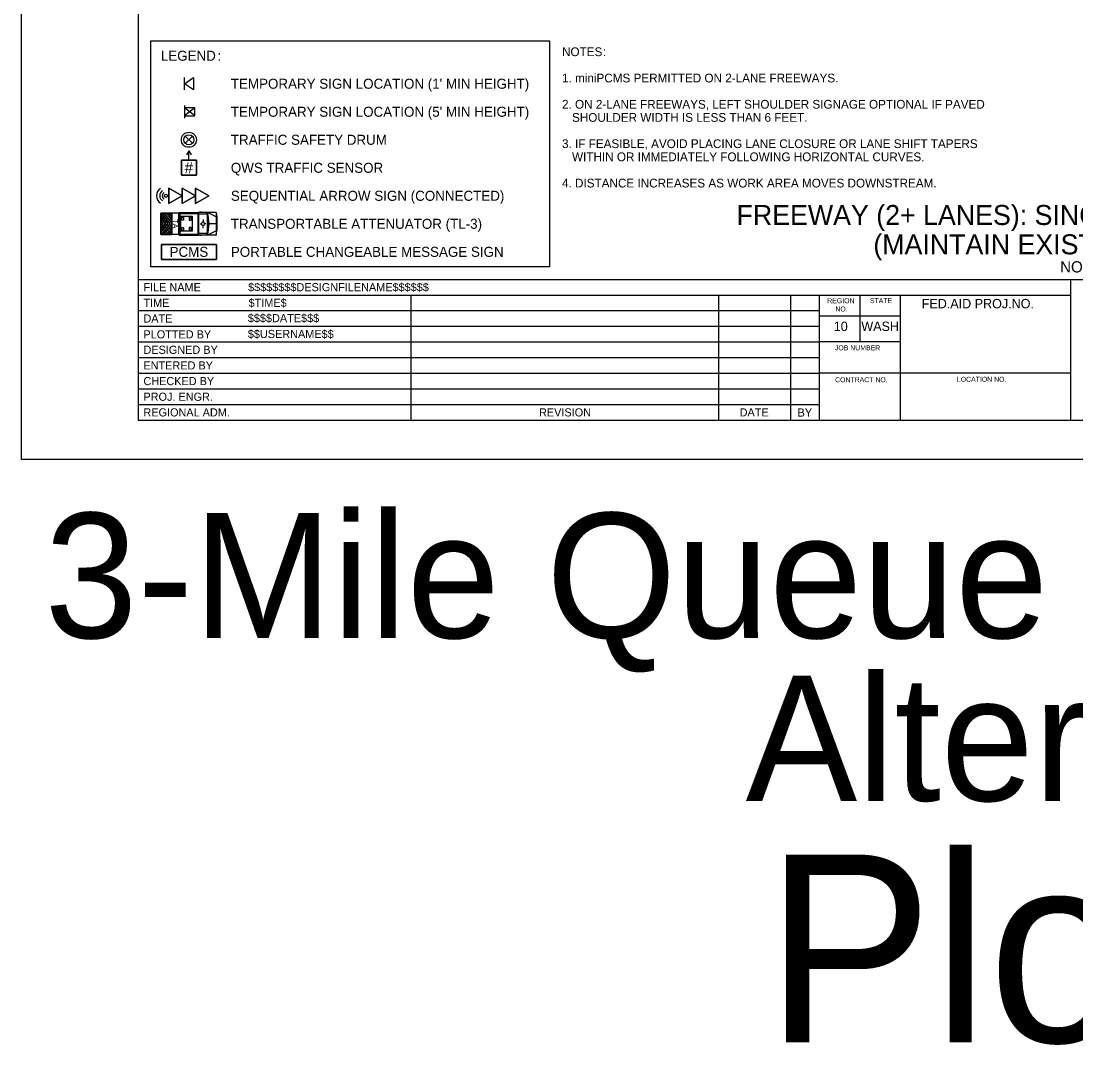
# Model space of a CAD drawing. Extents: x 99999 to 100116, y 99995 to 100013.
# Drawn here: x 100019.06 to 100027.5, y 99995.01 to 100003.19 of the extents above; entities that cross this region are included whole.
import ezdxf

# ---------------------------------------------------------------- set-up
doc = ezdxf.new("R2010")
doc.units = 0
for name, color, linetype in [('SH_DE_DetailHeading1Text', 7, 'Continuous'), ('SH_GI_GeneralNotesBodyText', 7, 'Continuous'), ('SH_GI_PlotLimits', 7, 'Continuous'), ('SH_GI_SheetBorder', 7, 'Continuous'), ('SH_GI_SheetLocationText', 7, 'Continuous'), ('SH_GI_SheetTextInCells', 7, 'Continuous'), ('SH_GI_TitleBlockText', 7, 'Continuous'), ('TR_WZ_PCMS', 7, 'Continuous'), ('TR_WZ_PortableSignMount5ftMinBlk-Wht', 7, 'Continuous'), ('TR_WZ_PortableSignMountBlk-Wht', 7, 'Continuous'), ('TR_WZ_SequentialArrowSign', 7, 'Continuous'), ('TR_WZ_TrafficSafetyDrum', 7, 'Continuous'), ('TR_WZ_TransportableAttenuator', 7, 'Continuous'), ('TR_WZ_WorkZoneDetails', 7, 'Continuous'), ('TR_WZ_WorkZoneTextCurrent', 7, 'Continuous')]:
    doc.layers.add(name, color=color, linetype=linetype)

msp = doc.modelspace()

# ---------------------------------------------------------------- linework, layer by layer
at = {"layer": 'SH_GI_PlotLimits'}
msp.add_lwpolyline([(100019.0625, 99999.6875), (100036.0625, 99999.6875), (100036.0625, 100010.6875), (100019.0625, 100010.6875)], close=True, dxfattribs=at)
at = {"layer": 'SH_GI_SheetBorder'}
for p, q in [((100020, 100010.375), (100020, 100000)), ((100020, 100001.1259), (100035.75, 100001.1259)), ((100027.4566, 100000), (100027.4566, 100001.1259)), ((100020, 100001.0008), (100027.4566, 100001.0008)), ((100022.179, 100001.0008), (100022.179, 100000)), ((100024.641, 100001.0008), (100024.641, 100000)), ((100025.2164, 100001.0008), (100025.2164, 100000)), ((100025.4451, 100001.0008), (100025.4451, 100000)), ((100025.7719, 100000.6255), (100025.7719, 100001.0008)), ((100026.0956, 100000), (100026.0956, 100001.0008)), ((100020, 100000.8757), (100022.1821, 100000.8757)), ((100022.1821, 100000.8757), (100025.4466, 100000.8757)), ((100026.0958, 100000.831), (100025.4466, 100000.831)), ((100020, 100000.7506), (100022.1821, 100000.7506)), ((100022.1821, 100000.7506), (100025.4466, 100000.7506)), ((100020, 100000.6255), (100025.4466, 100000.6255)), ((100026.0958, 100000.6255), (100025.4466, 100000.6255)), ((100020, 100000.5004), (100025.4466, 100000.5004)), ((100020, 100000.3753), (100025.4466, 100000.3753)), ((100027.4566, 100000.3753), (100025.4466, 100000.3753)), ((100020, 100000.2502), (100025.4466, 100000.2502)), ((100020, 100000.1251), (100025.4466, 100000.1251)), ((100020, 100000), (100035.75, 100000))]:
    msp.add_line(p, q, dxfattribs=at)
at = {"layer": 'TR_WZ_PCMS'}
for points in [[(100020.6241, 100001.4059), (100020.6241, 100001.2859), (100020.1841, 100001.2859), (100020.1841, 100001.4059), (100020.6241, 100001.4059)], [(100020.1841, 100001.4059), (100020.1841, 100001.2859), (100020.6241, 100001.2859), (100020.6241, 100001.4059), (100020.1841, 100001.4059)]]:
    msp.add_lwpolyline(points, dxfattribs=at)
at = {"layer": 'TR_WZ_PortableSignMount5ftMinBlk-Wht'}
for p, q in [((100020.3682, 100002.5159), (100020.3682, 100002.4159)), ((100020.4516, 100002.4334), (100020.3682, 100002.4984)), ((100020.4516, 100002.4984), (100020.3682, 100002.4334)), ((100020.4099, 100002.4659), (100020.4099, 100002.4659)), ((100020.41, 100002.4658), (100020.41, 100002.4658))]:
    msp.add_line(p, q, dxfattribs=at)
msp.add_lwpolyline([(100020.4516, 100002.4334), (100020.4516, 100002.4984), (100020.3682, 100002.4984), (100020.3682, 100002.4334)], close=True, dxfattribs=at)
at = {"layer": 'TR_WZ_PortableSignMountBlk-Wht'}
msp.add_line((100020.3682, 100002.64), (100020.3682, 100002.74), dxfattribs=at)
msp.add_lwpolyline([(100020.3682, 100002.6899), (100020.44, 100002.74), (100020.44, 100002.64)], close=True, dxfattribs=at)
at = {"layer": 'TR_WZ_SequentialArrowSign'}
for points in [[(100020.3508, 100001.7939), (100020.2441, 100001.7321), (100020.2441, 100001.8557), (100020.3508, 100001.7939)], [(100020.2441, 100001.8557), (100020.2441, 100001.7321), (100020.3508, 100001.7939), (100020.2441, 100001.8557)], [(100020.4575, 100001.7939), (100020.3508, 100001.7321), (100020.3508, 100001.7939), (100020.3508, 100001.8557), (100020.4575, 100001.7939)], [(100020.3508, 100001.8557), (100020.3508, 100001.7939), (100020.3508, 100001.7321), (100020.4575, 100001.7939), (100020.3508, 100001.8557)], [(100020.5641, 100001.7939), (100020.4575, 100001.7321), (100020.4575, 100001.7939), (100020.4575, 100001.8557), (100020.5641, 100001.7939)], [(100020.4575, 100001.8557), (100020.4575, 100001.7939), (100020.4575, 100001.7321), (100020.5641, 100001.7939), (100020.4575, 100001.8557)]]:
    msp.add_lwpolyline(points, dxfattribs=at)
msp.add_circle((100020.2216, 100001.7939), 0.0125, dxfattribs=at)
for radius, start, end in [(0.075, 127.32912, 232.67088), (0.05, 123.97816, 236.02184), (0.03, 117.15796, 242.84204)]:
    msp.add_arc((100020.2216, 100001.7939), radius, start, end, dxfattribs=at)
at = {"layer": 'TR_WZ_TrafficSafetyDrum'}
for p, q in [((100020.4324, 100002.2701), (100020.3758, 100002.2136)), ((100020.4324, 100002.2136), (100020.3758, 100002.2701))]:
    msp.add_line(p, q, dxfattribs=at)
for radius in [0.06, 0.06, 0.04]:
    msp.add_circle((100020.4041, 100002.2419), radius, dxfattribs=at)
at = {"layer": 'TR_WZ_TransportableAttenuator'}
for p, q in [((100020.1791, 100001.6385), (100020.2355, 100001.5706)), ((100020.1791, 100001.6167), (100020.1791, 100001.6385)), ((100020.2355, 100001.5706), (100020.1791, 100001.6385)), ((100020.1791, 100001.6385), (100020.1791, 100001.6167)), ((100020.2551, 100001.5701), (100020.185, 100001.6546)), ((100020.185, 100001.6546), (100020.2041, 100001.6546)), ((100020.185, 100001.6546), (100020.2551, 100001.5701)), ((100020.2041, 100001.6546), (100020.185, 100001.6546)), ((100020.2041, 100001.6546), (100020.2676, 100001.5776)), ((100020.2676, 100001.5776), (100020.2041, 100001.6546)), ((100020.2676, 100001.6025), (100020.2248, 100001.6546)), ((100020.2248, 100001.6546), (100020.2439, 100001.6546)), ((100020.2439, 100001.6546), (100020.2248, 100001.6546)), ((100020.2248, 100001.6546), (100020.2676, 100001.6025)), ((100020.2439, 100001.6546), (100020.2676, 100001.626)), ((100020.2676, 100001.626), (100020.2439, 100001.6546)), ((100020.2676, 100001.4857), (100020.2676, 100001.6546)), ((100020.3279, 100001.6546), (100020.2676, 100001.6546)), ((100020.3208, 100001.6515), (100020.3208, 100001.4884)), ((100020.3241, 100001.657), (100020.3274, 100001.657)), ((100020.3274, 100001.657), (100020.3274, 100001.4829)), ((100020.3279, 100001.6599), (100020.4803, 100001.6599)), ((100020.3279, 100001.6599), (100020.3279, 100001.4799)), ((100020.3279, 100001.6543), (100020.3279, 100001.4857)), ((100020.3323, 100001.6528), (100020.3323, 100001.4871)), ((100020.3323, 100001.6528), (100020.476, 100001.6528)), ((100020.476, 100001.6528), (100020.476, 100001.4871)), ((100020.4803, 100001.6599), (100020.4803, 100001.4799)), ((100020.4824, 100001.6599), (100020.4824, 100001.4799)), ((100020.6223, 100001.6599), (100020.4824, 100001.6599)), ((100020.551, 100001.646), (100020.4824, 100001.646)), ((100020.5014, 100001.6625), (100020.493, 100001.6625)), ((100020.551, 100001.6599), (100020.5421, 100001.646)), ((100020.551, 100001.6599), (100020.551, 100001.4799)), ((100020.5523, 100001.6599), (100020.5523, 100001.4799)), ((100020.6223, 100001.627), (100020.5523, 100001.6599)), ((100020.6223, 100001.6599), (100020.6223, 100001.4799)), ((100020.6223, 100001.6599), (100020.6291, 100001.6236)), ((100020.2174, 100001.5709), (100020.1791, 100001.6167)), ((100020.1791, 100001.6167), (100020.2174, 100001.5709)), ((100020.1791, 100001.5935), (100020.1987, 100001.5702)), ((100020.1791, 100001.5467), (100020.1791, 100001.5935)), ((100020.1987, 100001.5702), (100020.1791, 100001.5935)), ((100020.1791, 100001.5935), (100020.1791, 100001.5467)), ((100020.1791, 100001.5248), (100020.2174, 100001.5709)), ((100020.2174, 100001.5709), (100020.1791, 100001.5248)), ((100020.2355, 100001.5706), (100020.1791, 100001.5027)), ((100020.1791, 100001.5027), (100020.2355, 100001.5706)), ((100020.1987, 100001.5702), (100020.1791, 100001.5467)), ((100020.1791, 100001.5467), (100020.1987, 100001.5702)), ((100020.1849, 100001.4855), (100020.2551, 100001.5701)), ((100020.2551, 100001.5701), (100020.1849, 100001.4855)), ((100020.2676, 100001.5625), (100020.2037, 100001.4855)), ((100020.2037, 100001.4855), (100020.2676, 100001.5625)), ((100020.2676, 100001.626), (100020.2676, 100001.6025)), ((100020.2676, 100001.6025), (100020.2676, 100001.626)), ((100020.2676, 100001.5776), (100020.2676, 100001.5625)), ((100020.2676, 100001.5625), (100020.2676, 100001.5776)), ((100020.3208, 100001.5826), (100020.3274, 100001.5793)), ((100020.3208, 100001.5573), (100020.3274, 100001.5607)), ((100020.3226, 100001.57), (100020.3257, 100001.57)), ((100020.3241, 100001.5725), (100020.3241, 100001.5674)), ((100020.4951, 100001.5701), (100020.5045, 100001.57)), ((100020.507, 100001.5696), (100020.507, 100001.5696)), ((100020.5175, 100001.6056), (100020.5175, 100001.5911)), ((100020.5398, 100001.5701), (100020.5305, 100001.57)), ((100020.6223, 100001.57), (100020.566, 100001.57)), ((100020.6291, 100001.6236), (100020.6291, 100001.5163)), ((100020.1791, 100001.5027), (100020.1791, 100001.5248)), ((100020.1791, 100001.5248), (100020.1791, 100001.5027)), ((100020.2037, 100001.4855), (100020.1849, 100001.4855)), ((100020.1849, 100001.4855), (100020.2037, 100001.4855)), ((100020.2243, 100001.4855), (100020.2676, 100001.5376)), ((100020.2676, 100001.5376), (100020.2243, 100001.4855)), ((100020.2446, 100001.4855), (100020.2243, 100001.4855)), ((100020.2243, 100001.4855), (100020.2446, 100001.4855)), ((100020.2676, 100001.5128), (100020.2446, 100001.4855)), ((100020.2446, 100001.4855), (100020.2676, 100001.5128)), ((100020.2676, 100001.5376), (100020.2676, 100001.5128)), ((100020.2676, 100001.5128), (100020.2676, 100001.5376)), ((100020.3279, 100001.4857), (100020.2676, 100001.4857)), ((100020.3241, 100001.4829), (100020.3274, 100001.4829)), ((100020.3279, 100001.4799), (100020.4803, 100001.4799)), ((100020.3323, 100001.4871), (100020.476, 100001.4871)), ((100020.551, 100001.4939), (100020.4824, 100001.4939)), ((100020.6223, 100001.4799), (100020.4824, 100001.4799)), ((100020.5014, 100001.4774), (100020.493, 100001.4774)), ((100020.5175, 100001.5343), (100020.5175, 100001.5488)), ((100020.5437, 100001.4939), (100020.551, 100001.4799)), ((100020.6223, 100001.5129), (100020.5523, 100001.4799)), ((100020.6223, 100001.4799), (100020.6291, 100001.5163))]:
    msp.add_line(p, q, dxfattribs=at)
for points in [[(100020.2676, 100001.4855), (100020.1791, 100001.4855), (100020.1791, 100001.6546), (100020.2676, 100001.6546)], [(100020.3398, 100001.63), (100020.4298, 100001.63), (100020.4298, 100001.51), (100020.3398, 100001.51)], [(100020.3473, 100001.6225), (100020.3623, 100001.6225), (100020.3623, 100001.6), (100020.3473, 100001.6)], [(100020.4223, 100001.6225), (100020.4073, 100001.6225), (100020.4073, 100001.6), (100020.4223, 100001.6)], [(100020.3473, 100001.54), (100020.3623, 100001.54), (100020.3623, 100001.5175), (100020.3473, 100001.5175)], [(100020.4223, 100001.54), (100020.4073, 100001.54), (100020.4073, 100001.5175), (100020.4223, 100001.5175)]]:
    msp.add_lwpolyline(points, close=True, dxfattribs=at)
msp.add_lwpolyline([(100020.2676, 100001.6546), (100020.1791, 100001.6546), (100020.1791, 100001.4855), (100020.2676, 100001.4857)], dxfattribs=at)
for centre, major_axis, start_param, end_param in [((100020.3241, 100001.6515), (0, 0.00549), 6.283185, 7.853982), ((100020.4523, 100001.5699), (0, 0.1889), 4.215852, 5.209111), ((100020.3241, 100001.4884), (0, -0.00549), 4.712389, 6.283185)]:
    msp.add_ellipse(centre, major_axis=major_axis, ratio=0.60201, start_param=start_param, end_param=end_param, dxfattribs=at)
for centre, major_axis in [((100020.3241, 100001.5699), (0, -0.00254)), ((100020.5175, 100001.5699), (0, -0.0173))]:
    msp.add_ellipse(centre, major_axis=major_axis, ratio=0.60201, dxfattribs=at)
at = {"layer": 'TR_WZ_WorkZoneDetails'}
for p, q in [((100020.4041, 100002.1529), (100020.3854, 100002.1204)), ((100020.4041, 100002.0779), (100020.4041, 100002.1529)), ((100020.4041, 100002.1529), (100020.4229, 100002.1204))]:
    msp.add_line(p, q, dxfattribs=at)
msp.add_lwpolyline([(100020.3441, 100002.0779), (100020.4641, 100002.0779), (100020.4641, 100001.9579), (100020.3441, 100001.9579)], close=True, dxfattribs=at)
msp.add_lwpolyline([(100020.3441, 100002.0779), (100020.3441, 100001.9579), (100020.4641, 100001.9579), (100020.4641, 100002.0779), (100020.4041, 100002.0779), (100020.3441, 100002.0779)], dxfattribs=at)
at = {"layer": 'TR_WZ_WorkZoneTextCurrent'}
msp.add_lwpolyline([(100020.1, 100003.0339), (100023.2886, 100003.0339), (100023.2886, 100001.2259), (100020.1, 100001.2259)], close=True, dxfattribs=at)

# ---------------------------------------------------------------- texts
at = {"layer": 'SH_DE_DetailHeading1Text'}
for s, height, p in [('FREEWAY (2+ LANES): SINGLE RIGHT LANE CLOSURE', 0.16, (100024.7843, 100001.5606)), ('(MAINTAIN EXISTING SPEED LIMIT)', 0.16, (100025.8785, 100001.3259)), ('NOT TO SCALE', 0.09, (100027.3725, 100001.1809))]:
    msp.add_text(s, height=height, rotation=360, dxfattribs=at).set_placement(p)
at = {"layer": 'SH_GI_GeneralNotesBodyText'}
for s, p in [('NOTES', (100023.3886, 100002.9106)), (':', (100023.7161, 100002.9106)), ('1. miniPCMS PERMITTED ON 2-LANE FREEWAYS.', (100023.3886, 100002.7006)), ('2. ON 2-LANE FREEWAYS, LEFT SHOULDER SIGNAGE OPTIONAL IF PAVED ', (100023.3886, 100002.4906)), ('SHOULDER WIDTH IS LESS THAN 6 FEET.', (100023.4686, 100002.3856)), ('3. IF FEASIBLE, AVOID PLACING LANE CLOSURE OR LANE SHIFT TAPERS ', (100023.3886, 100002.1756)), ('WITHIN OR IMMEDIATELY FOLLOWING HORIZONTAL CURVES.', (100023.4686, 100002.0706)), ('4. DISTANCE INCREASES AS WORK AREA MOVES DOWNSTREAM.', (100023.3886, 100001.8606))]:
    msp.add_text(s, height=0.07, rotation=360, dxfattribs=at).set_placement(p)
at = {"layer": 'SH_GI_SheetLocationText'}
for s, height, p in [('3-Mile Queue Warning System', 1, (100019.2499, 99998.258)), ('Alternative', 1, (100024.8575, 99996.9562)), ('Plot 2', 1.5, (100025.015, 99995.0267))]:
    msp.add_text(s, height=height, dxfattribs=at).set_placement(p)
at = {"layer": 'SH_GI_SheetTextInCells'}
for s, height, p in [('FILE NAME', 0.06505, (100020.041, 100001.0308)), ('TIME', 0.06505, (100020.041, 100000.9057)), ('REGION', 0.04003, (100025.5099, 100000.9352)), ('STATE', 0.04003, (100025.8511, 100000.9357)), ('FED.AID PROJ.NO.', 0.07506, (100026.2652, 100000.8945)), ('NO.', 0.04003, (100025.5752, 100000.869)), ('DATE', 0.06505, (100020.041, 100000.7806)), ('PLOTTED BY', 0.06505, (100020.041, 100000.6538)), ('10', 0.07506, (100025.5621, 100000.7131)), ('WASH', 0.07506, (100025.7826, 100000.7131)), ('DESIGNED BY', 0.065052, (100020.041, 100000.5304)), ('JOB NUMBER', 0.04003, (100025.5712, 100000.5587)), ('ENTERED BY', 0.06505, (100020.041, 100000.4053)), ('CHECKED BY', 0.06505, (100020.041, 100000.2802)), ('CONTRACT NO.', 0.040032, (100025.5725, 100000.3037)), ('LOCATION NO.', 0.040032, (100026.5465, 100000.3067)), ('PROJ. ENGR.', 0.065052, (100020.041, 100000.1551)), ('REGIONAL ADM.', 0.065052, (100020.041, 100000.03)), ('REVISION', 0.06505, (100023.2048, 100000.03)), ('DATE', 0.06505, (100024.8091, 100000.03)), ('BY', 0.06505, (100025.2725, 100000.0285))]:
    msp.add_text(s, height=height, dxfattribs=at).set_placement(p)
at = {"layer": 'SH_GI_TitleBlockText'}
for s, height, p in [('$$$$$$$$DESIGNFILENAME$$$$$$', 0.065052, (100020.8775, 100001.0308)), ('$TIME$', 0.06505, (100020.882, 100000.9059)), ('$$$$DATE$$$', 0.065052, (100020.8759, 100000.7835)), ('$$USERNAME$$', 0.065052, (100020.8759, 100000.6567))]:
    msp.add_text(s, height=height, dxfattribs=at).set_placement(p)
at = {"layer": 'TR_WZ_PCMS'}
msp.add_text('PCMS', height=0.08, rotation=360, dxfattribs=at).set_placement((100020.2502, 100001.3059))
at = {"layer": 'TR_WZ_TransportableAttenuator'}
msp.add_text('TA', height=0.045, rotation=269.99999, dxfattribs=at).set_placement((100020.2717, 100001.6094))
at = {"layer": 'TR_WZ_WorkZoneDetails'}
msp.add_text('#', height=0.09, dxfattribs=at).set_placement((100020.3702, 100001.9729))
at = {"layer": 'TR_WZ_WorkZoneTextCurrent'}
for s, p in [('LEGEND', (100020.18, 100002.8739)), (':', (100020.6328, 100002.8739)), ("TEMPORARY SIGN LOCATION (1' MIN HEIGHT)", (100020.74, 100002.6499)), ("TEMPORARY SIGN LOCATION (5' MIN HEIGHT)", (100020.74, 100002.4259)), ('TRAFFIC SAFETY DRUM', (100020.74, 100002.2019)), ('QWS TRAFFIC SENSOR', (100020.74, 100001.9779)), ('SEQUENTIAL ARROW SIGN (CONNECTED)', (100020.74, 100001.7539)), ('TRANSPORTABLE ATTENUATOR (TL-3)', (100020.74, 100001.5299)), ('PORTABLE CHANGEABLE MESSAGE SIGN', (100020.74, 100001.3059))]:
    msp.add_text(s, height=0.08, rotation=360, dxfattribs=at).set_placement(p)

doc.saveas('drawing.dxf')
